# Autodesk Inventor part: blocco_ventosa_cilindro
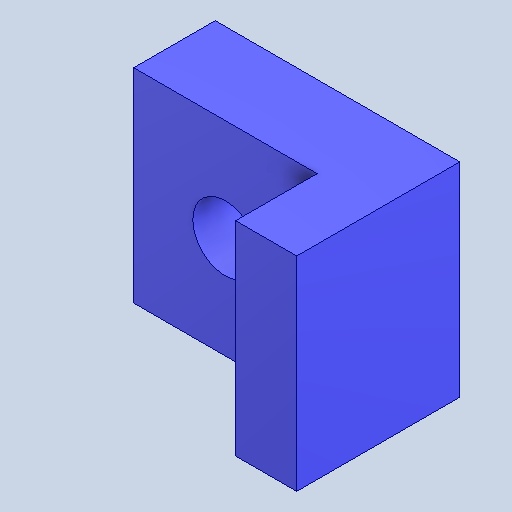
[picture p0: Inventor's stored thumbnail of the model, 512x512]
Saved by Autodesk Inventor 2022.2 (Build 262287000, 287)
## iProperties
Created: 2024-10
Part Number: blocco_ventosa_cilindro
Material: Alluminio 6061
Document SubType Name: Modeling
Designer: 18907419
Density: 2.7 g/cm^3
Appearance: Default
Author: 18907419
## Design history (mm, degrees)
feature "Solido1"
node "Solido2"
